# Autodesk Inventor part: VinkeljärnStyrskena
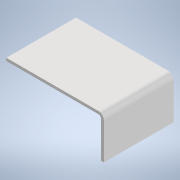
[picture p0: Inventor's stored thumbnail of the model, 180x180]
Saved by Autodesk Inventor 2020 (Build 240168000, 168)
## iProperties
Created: 2019-07
Part Number: VinkeljärnStyrskena
Material: Generic
Document SubType Name: Sheet Metal
Designer: cl
Density: 1 g/cm^3
Sheet Metal Rule: Default_mm
Appearance: Default
Author: cl
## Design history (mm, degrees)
node "Face1"
  sketch "Sketch2"
    geometry: L1 (0, 0)-(140, 0); L2 (140, 0)-(140, -100); L3 (140, -100)-(0, -100); L4 (0, -100)-(0, 0)
    constraints: 8 end point, 2 parallel, 1 horizontal, 1 perpendicular
    dimensions: "d0" = 140 distance of L2.end L3.end; "d1" = 100 distance of L1.end L2.end
node "Flange1"
body "Solid1"
face "Plate1" dims "d2" = 4 (= Thickness)
sketch "Sketch3"
  geometry: L1 through (0, 50) direction (0, -1); L2 through (30, 0) direction (1, 0); L3 (60, 0)-(60, 100); L4 (60, 100)-(0, 100)
  constraints: 6 end point, 1 horizontal, 1 perpendicular, 1 vertical
face "Plate2" dims "d2" = 4 (= Thickness), "d3" = 4 (= BendReliefWidth), "d4" = 2 (= BendReliefDepth), "d5" = 8 (= MinimumRemnant), "d6" = 4 (= TransitionRadius), "d7" = 60, "d8" = -90 deg, "d9" = 4 (= BendRadius), "d10" = 16 (= CornerReliefSize), "d11" = 4 (= GapSize), "d12" = 4 (= JacobiRadiusSize), "SeamGap" = 0.01
bend "Bend1" dims "d2" = 4 (= Thickness), "d3" = 4 (= BendReliefWidth), "d4" = 2 (= BendReliefDepth), "d5" = 8 (= MinimumRemnant), "d6" = 4 (= TransitionRadius), "d7" = 60, "d8" = -90 deg, "d9" = 4 (= BendRadius), "SeamGap" = 0.01
feature "Corner1" dims "d7" = 60, "d8" = -90 deg, "d10" = 16 (= CornerReliefSize), "d11" = 4 (= GapSize), "d12" = 4 (= JacobiRadiusSize)
other parameters: "Thickness" = 4 (derived), "KFactor" = 4.4, "BendRadius" = 4 (= Thickness), "BendReliefWidth" = 4 (= Thickness), "BendReliefDepth" = 2 (= 0.5 x Thickness), "CornerReliefSize" = 16 (= 4 x Thickness), "MinimumRemnant" = 8 (= 2 x Thickness), "TransitionRadius" = 4 (= BendRadius), "JacobiRadiusSize" = 4 (= BendRadius), "GapSize" = 4 (= Thickness)
